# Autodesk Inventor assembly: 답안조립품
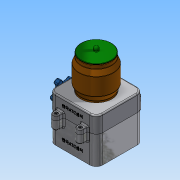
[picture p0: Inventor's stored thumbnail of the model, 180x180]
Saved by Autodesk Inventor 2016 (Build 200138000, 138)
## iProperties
Created: 2018-01
Part Number: 답안조립품
Material: 일반
Document SubType Name: Assembly
Designer: Administrator
Author: Administrator
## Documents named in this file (9)
- C:\Users\Administrator\Desktop\480107V1027\답안조립품.iam
- C:\Users\Administrator\Desktop\480107V1027\본체.ipt
- C:\Users\Administrator\Desktop\480107V1027\용기.ipt
- C:\Users\Administrator\Desktop\480107V1027\본체커버.ipt
- C:\Users\Administrator\Desktop\480107V1027\핸들축.ipt
- C:\Users\Administrator\Desktop\480107V1027\핸들.ipt
- C:\Users\Administrator\Desktop\480107V1027\볼트 M3x12.ipt
- C:\Users\Administrator\Desktop\480107V1027\용기캡.ipt
- C:\Users\Administrator\Desktop\480107V1027\볼트 M4x12.ipt
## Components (2 placed, 2 different names)
1. 핸들축:1
2. 핸들:1
